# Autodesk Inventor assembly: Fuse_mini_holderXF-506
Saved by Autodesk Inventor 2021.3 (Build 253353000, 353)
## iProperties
Created: 2022-06
Part Number: Fuse_mini_holderXF-506
Document SubType Name: Assembly
Designer: Administrator
Title: Fuse_mini_holderXF-506
Author: Administrator
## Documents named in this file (2)
- c:\worker\convert-fusion-r03\tmp\job-1\203\output\files\98ba3c1f-9f0e-47fe-8659-38db50984f0d\Fuse_mini_holderXF-506.iam
- c:\worker\convert-fusion-r03\tmp\job-1\203\output\files\98ba3c1f-9f0e-47fe-8659-38db50984f0d\COMPOUND (2).ipt
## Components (1 placed, 1 different names)
1. COMPOUND (2):1
